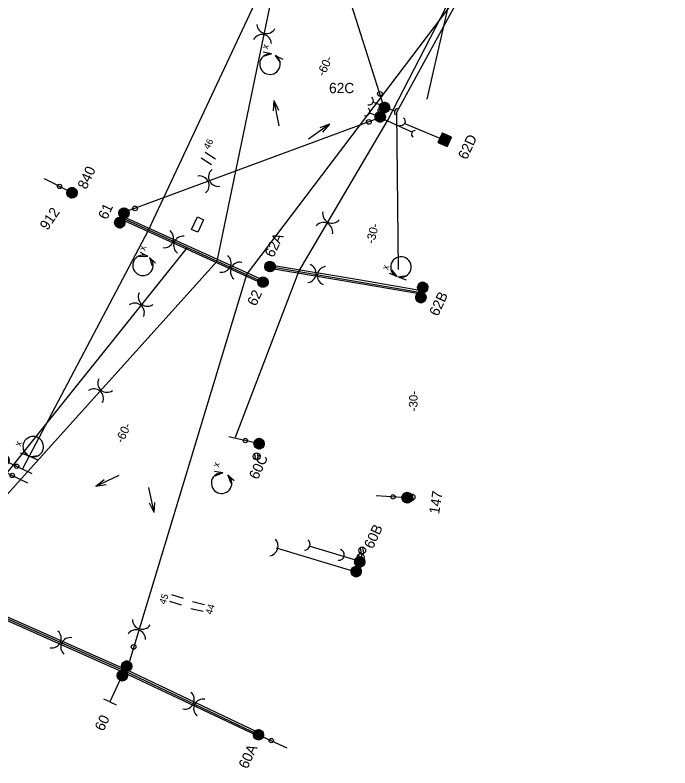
# Model space of a CAD drawing. Extents: x -595867 to -593796, y -1159595 to -1157495.
# Drawn here: x -594848.4 to -594752.7, y -1158325.2 to -1158215.3 of the extents above; entities that cross this region are included whole.
import ezdxf

# ---------------------------------------------------------------- set-up
doc = ezdxf.new("R2010")
doc.units = 0
doc.layers.add('BVK_kanalizace_destova_nova', color=7, linetype='Continuous')
doc.layers.add('BVK_kanalizace_jednotna_nova', color=7, linetype='Continuous')

# ---------------------------------------------------------------- blocks, each defined once
blk = doc.blocks.new('st_bp')
for p, q in [((0.0075, 0.0075), (-0.0075, 0.0075)), ((-0.0075, 0.0075), (-0.0075, -0.0075)), ((-0.0075, -0.0075), (0.0075, 0.0075)), ((-0.0075, -0.0071), (0.0071, 0.0075)), ((-0.0075, -0.0067), (0.0067, 0.0075)), ((-0.0075, -0.0062), (0.0062, 0.0075)), ((-0.0075, -0.0058), (0.0058, 0.0075)), ((-0.0075, -0.0054), (0.0054, 0.0075)), ((-0.0075, -0.005), (0.005, 0.0075)), ((-0.0075, -0.0045), (0.0045, 0.0075)), ((-0.0075, -0.0041), (0.0041, 0.0075)), ((-0.0075, -0.0037), (0.0037, 0.0075)), ((-0.0075, -0.0033), (0.0033, 0.0075)), ((-0.0075, -0.0028), (0.0028, 0.0075)), ((-0.0075, -0.0024), (0.0024, 0.0075)), ((-0.0075, -0.002), (0.002, 0.0075)), ((-0.0075, -0.0016), (0.0016, 0.0075)), ((-0.0075, -0.0011), (0.0011, 0.0075)), ((-0.0075, -0.0007), (0.0007, 0.0075)), ((-0.0075, -0.0003), (0.0003, 0.0075)), ((-0.0075, 0.0001), (-0.0001, 0.0075)), ((-0.0075, 0.0006), (-0.0006, 0.0075)), ((-0.0075, 0.001), (-0.001, 0.0075)), ((-0.0075, 0.0014), (-0.0014, 0.0075)), ((-0.0075, 0.0018), (-0.0018, 0.0075)), ((-0.0075, 0.0023), (-0.0023, 0.0075)), ((-0.0075, 0.0027), (-0.0027, 0.0075)), ((-0.0075, 0.0031), (-0.0031, 0.0075)), ((-0.0075, 0.0035), (-0.0035, 0.0075)), ((-0.0075, 0.004), (-0.004, 0.0075)), ((-0.0075, 0.0044), (-0.0044, 0.0075)), ((-0.0075, 0.0048), (-0.0048, 0.0075)), ((-0.0075, 0.0052), (-0.0052, 0.0075)), ((-0.0075, 0.0057), (-0.0057, 0.0075)), ((-0.0075, 0.0061), (-0.0061, 0.0075)), ((-0.0075, 0.0065), (-0.0065, 0.0075)), ((-0.0075, 0.0069), (-0.0069, 0.0075)), ((-0.0075, 0.0073), (-0.0073, 0.0075)), ((-0.0071, -0.0075), (0.0075, 0.0071)), ((-0.0067, -0.0075), (0.0075, 0.0067)), ((-0.0062, -0.0075), (0.0075, 0.0062)), ((-0.0058, -0.0075), (0.0075, 0.0058)), ((-0.0054, -0.0075), (0.0075, 0.0054)), ((-0.005, -0.0075), (0.0075, 0.005)), ((-0.0045, -0.0075), (0.0075, 0.0045)), ((-0.0041, -0.0075), (0.0075, 0.0041)), ((-0.0037, -0.0075), (0.0075, 0.0037)), ((-0.0033, -0.0075), (0.0075, 0.0033)), ((-0.0028, -0.0075), (0.0075, 0.0028)), ((-0.0024, -0.0075), (0.0075, 0.0024)), ((-0.002, -0.0075), (0.0075, 0.002)), ((-0.0016, -0.0075), (0.0075, 0.0016)), ((-0.0011, -0.0075), (0.0075, 0.0011)), ((-0.0007, -0.0075), (0.0075, 0.0007)), ((-0.0003, -0.0075), (0.0075, 0.0003)), ((0.0075, -0.0075), (0.0075, 0.0075)), ((-0.0075, -0.0075), (0.0075, -0.0075)), ((0.0001, -0.0075), (0.0075, -0.0001)), ((0.0006, -0.0075), (0.0075, -0.0006)), ((0.001, -0.0075), (0.0075, -0.001)), ((0.0014, -0.0075), (0.0075, -0.0014)), ((0.0018, -0.0075), (0.0075, -0.0018)), ((0.0023, -0.0075), (0.0075, -0.0023)), ((0.0027, -0.0075), (0.0075, -0.0027)), ((0.0031, -0.0075), (0.0075, -0.0031)), ((0.0035, -0.0075), (0.0075, -0.0035)), ((0.004, -0.0075), (0.0075, -0.004)), ((0.0044, -0.0075), (0.0075, -0.0044)), ((0.0048, -0.0075), (0.0075, -0.0048)), ((0.0052, -0.0075), (0.0075, -0.0052)), ((0.0057, -0.0075), (0.0075, -0.0057)), ((0.0061, -0.0075), (0.0075, -0.0061)), ((0.0065, -0.0075), (0.0075, -0.0065)), ((0.0069, -0.0075), (0.0075, -0.0069)), ((0.0073, -0.0075), (0.0075, -0.0073))]:
    blk.add_line(p, q)
blk = doc.blocks.new('st_2t')
for points in [[(-0.0077, 0.0091), (0.0015, 0.0147), (0.0025, 0.0144), (-0.0078, 0.0082)], [(-0.0078, 0.0082), (0.0025, 0.0144), (0.0032, 0.014), (-0.0078, 0.0072)], [(-0.0078, 0.0072), (0.0032, 0.014), (0.004, 0.0135), (-0.0078, 0.0065)], [(-0.0078, 0.0065), (0.004, 0.0135), (0.0048, 0.0129), (-0.0076, 0.0056)], [(-0.0075, 0.0097), (0.0002, 0.0149), (0.0015, 0.0147), (-0.0077, 0.0091)], [(-0.0076, 0.0056), (0.0048, 0.0129), (0.0055, 0.0121), (-0.0073, 0.0044)], [(-0.0073, 0.0104), (-0.0005, 0.015), (0.0002, 0.0149), (-0.0075, 0.0097)], [(-0.0071, 0.0108), (-0.0019, 0.0148), (-0.0005, 0.015), (-0.0073, 0.0104)], [(-0.0073, 0.0044), (0.0055, 0.0121), (0.0063, 0.0109), (-0.0068, 0.0036)], [(-0.0066, 0.0115), (-0.0026, 0.0146), (-0.0019, 0.0148), (-0.0071, 0.0108)], [(-0.0062, 0.0122), (-0.0035, 0.0142), (-0.0026, 0.0146), (-0.0066, 0.0115)], [(-0.0056, 0.0128), (-0.0045, 0.0137), (-0.0035, 0.0142), (-0.0062, 0.0122)], [(-0.0068, 0.0036), (0.0063, 0.0109), (0.0067, 0.0097), (-0.006, 0.0026)], [(-0.006, 0.0026), (0.0067, 0.0097), (0.007, 0.0086), (-0.0052, 0.0018)], [(-0.0052, 0.0018), (0.007, 0.0086), (0.0071, 0.0071), (-0.0044, 0.0012)], [(-0.0044, 0.0012), (0.0071, 0.0071), (0.0069, 0.0057), (-0.0035, 0.0007)], [(-0.0035, 0.0007), (0.0069, 0.0057), (0.0066, 0.0047), (-0.0024, 0.0003)], [(-0.0024, 0.0003), (0.0066, 0.0047), (0.0061, 0.0038), (-0.0015, 0.0001)], [(-0.0015, 0.0001), (0.0061, 0.0038), (0.0055, 0.0029), (-0.0009, 0)], [(-0.0009, 0), (0.0055, 0.0029), (0.005, 0.0022), (0, 0)], [(0, 0), (0.005, 0.0022), (0.0041, 0.0015), (0.001, 0.0001)], [(0.001, 0.0001), (0.0041, 0.0015), (0.0035, 0.001), (0.0021, 0.0004)], [(0.0021, 0.0004), (0.0035, 0.001), (0.0026, 0.0006), (0.0026, 0.0005)], [(-0.0077, -0.0059), (0.0015, -0.0003), (0.0025, -0.0006), (-0.0078, -0.0068)], [(-0.0078, -0.0068), (0.0025, -0.0006), (0.0032, -0.001), (-0.0078, -0.0078)], [(-0.0078, -0.0078), (0.0032, -0.001), (0.004, -0.0015), (-0.0078, -0.0085)], [(-0.0078, -0.0085), (0.004, -0.0015), (0.0048, -0.0021), (-0.0076, -0.0094)], [(-0.0075, -0.0053), (0.0002, -0.0001), (0.0015, -0.0003), (-0.0077, -0.0059)], [(-0.0076, -0.0094), (0.0048, -0.0021), (0.0055, -0.0029), (-0.0073, -0.0106)], [(-0.0073, -0.0046), (-0.0005, 0), (0.0002, -0.0001), (-0.0075, -0.0053)], [(-0.0071, -0.0042), (-0.0019, -0.0002), (-0.0005, 0), (-0.0073, -0.0046)], [(-0.0073, -0.0106), (0.0055, -0.0029), (0.0063, -0.0041), (-0.0068, -0.0114)], [(-0.0066, -0.0035), (-0.0026, -0.0004), (-0.0019, -0.0002), (-0.0071, -0.0042)], [(-0.0068, -0.0114), (0.0063, -0.0041), (0.0067, -0.0053), (-0.006, -0.0124)], [(-0.0062, -0.0028), (-0.0035, -0.0008), (-0.0026, -0.0004), (-0.0066, -0.0035)], [(-0.0056, -0.0022), (-0.0045, -0.0013), (-0.0035, -0.0008), (-0.0062, -0.0028)], [(-0.006, -0.0124), (0.0067, -0.0053), (0.007, -0.0064), (-0.0052, -0.0132)], [(-0.0052, -0.0132), (0.007, -0.0064), (0.0071, -0.0079), (-0.0044, -0.0138)], [(-0.0044, -0.0138), (0.0071, -0.0079), (0.0069, -0.0093), (-0.0035, -0.0143)], [(-0.0035, -0.0143), (0.0069, -0.0093), (0.0066, -0.0103), (-0.0024, -0.0147)], [(-0.0024, -0.0147), (0.0066, -0.0103), (0.0061, -0.0112), (-0.0015, -0.0149)], [(-0.0015, -0.0149), (0.0061, -0.0112), (0.0055, -0.0121), (-0.0009, -0.015)], [(-0.0009, -0.015), (0.0055, -0.0121), (0.005, -0.0128), (0, -0.015)], [(0, -0.015), (0.005, -0.0128), (0.0041, -0.0135), (0.001, -0.0149)], [(0.001, -0.0149), (0.0041, -0.0135), (0.0035, -0.014), (0.0021, -0.0146)], [(0.0021, -0.0146), (0.0035, -0.014), (0.0026, -0.0144), (0.0026, -0.0145)]]:
    blk.add_lwpolyline(points, close=True)
for centre in [(-0.0004, 0.0075), (-0.0004, -0.0075)]:
    blk.add_circle(centre, 0.0075)
blk = doc.blocks.new('st_1t')
for points in [[(-0.0074, 0.0007), (0.0028, 0.0069), (0.0036, 0.0066), (-0.0075, -0.0002)], [(-0.0075, -0.0002), (0.0036, 0.0066), (0.0044, 0.006), (-0.0074, -0.001)], [(-0.0073, 0.0016), (0.0019, 0.0072), (0.0028, 0.0069), (-0.0074, 0.0007)], [(-0.0074, -0.001), (0.0044, 0.006), (0.0052, 0.0054), (-0.0072, -0.0019)], [(-0.0071, 0.0022), (0.0006, 0.0074), (0.0019, 0.0072), (-0.0073, 0.0016)], [(-0.0072, -0.0019), (0.0052, 0.0054), (0.0059, 0.0046), (-0.0069, -0.003)], [(-0.0069, 0.0029), (-0.0001, 0.0075), (0.0006, 0.0074), (-0.0071, 0.0022)], [(-0.0067, 0.0033), (-0.0015, 0.0073), (-0.0001, 0.0075), (-0.0069, 0.0029)], [(-0.0069, -0.003), (0.0059, 0.0046), (0.0067, 0.0034), (-0.0064, -0.0039)], [(-0.0063, 0.004), (-0.0022, 0.0071), (-0.0015, 0.0073), (-0.0067, 0.0033)], [(-0.0064, -0.0039), (0.0067, 0.0034), (0.0071, 0.0022), (-0.0057, -0.0049)], [(-0.0058, 0.0047), (-0.0032, 0.0068), (-0.0022, 0.0071), (-0.0063, 0.004)], [(-0.0053, 0.0053), (-0.0041, 0.0062), (-0.0032, 0.0068), (-0.0058, 0.0047)], [(-0.0057, -0.0049), (0.0071, 0.0022), (0.0074, 0.0011), (-0.0049, -0.0056)], [(-0.0049, -0.0056), (0.0074, 0.0011), (0.0075, -0.0004), (-0.004, -0.0063)], [(-0.004, -0.0063), (0.0075, -0.0004), (0.0073, -0.0017), (-0.0032, -0.0068)], [(-0.0032, -0.0068), (0.0073, -0.0017), (0.007, -0.0027), (-0.0021, -0.0072)], [(-0.0021, -0.0072), (0.007, -0.0027), (0.0065, -0.0037), (-0.0011, -0.0074)], [(-0.0011, -0.0074), (0.0065, -0.0037), (0.0059, -0.0046), (-0.0005, -0.0075)], [(-0.0005, -0.0075), (0.0059, -0.0046), (0.0054, -0.0052), (0.0004, -0.0075)], [(0.0004, -0.0075), (0.0054, -0.0052), (0.0045, -0.006), (0.0014, -0.0074)], [(0.0014, -0.0074), (0.0045, -0.006), (0.0038, -0.0064), (0.0025, -0.007)], [(0.0025, -0.007), (0.0038, -0.0064), (0.0029, -0.0069), (0.0029, -0.0069)]]:
    blk.add_lwpolyline(points, close=True)
blk.add_circle((0, 0), 0.0075)
blk = doc.blocks.new('st_tecka')
blk.add_circle((0, 0), 0.00314)
blk = doc.blocks.new('st1k_konzola')
blk.add_line((0, 0), (0.0453, 0))
at = {"rotation": 90}
blk.add_blockref('st_tecka', (0.0205, 0), dxfattribs=at)
blk = doc.blocks.new('st_pk')
for p, q in [((0, 0), (0, -0.05)), ((0, -0.05), (-0.01, -0.05)), ((0, -0.05), (0.01, -0.05))]:
    blk.add_line(p, q)
blk = doc.blocks.new('st2k_2t')
for p, q in [((-0.0004, 0.0075), (0.0449, 0.0075)), ((-0.0004, -0.0075), (0.0449, -0.0075))]:
    blk.add_line(p, q)
blk.add_blockref('st_2t', (0, 0))
at = {"rotation": 90}
for p in [(0.0202, 0.0075), (0.0202, -0.0075)]:
    blk.add_blockref('st_tecka', p, dxfattribs=at)
blk = doc.blocks.new('st1k_1t')
blk.add_line((0, 0), (0.0453, 0))
blk.add_blockref('st_1t', (0, 0))
at = {"rotation": 90}
blk.add_blockref('st_tecka', (0.0205, 0), dxfattribs=at)
blk = doc.blocks.new('pol_delic')
for p, q in [((-0.005, -0.009), (-0.005, 0.009)), ((0.005, -0.009), (0.005, 0.009))]:
    blk.add_line(p, q)
blk = doc.blocks.new('pol_izol')
for centre, start, end in [((-0.0148, 0), 284.4047, 75.5953), ((0.0148, 0), 104.4047, 255.5953)]:
    blk.add_arc(centre, 0.0138, start, end)
blk = doc.blocks.new('pol_pevbod')
for q in [(0, 0), (0.0163, 0.0168), (0.0204, 0.0101)]:
    blk.add_line((0.0305, 0.0219), q)
blk = doc.blocks.new('pol_sjsp')
for p, q in [((-0.01, 0.005), (0.01, 0.005)), ((-0.01, -0.005), (-0.01, 0.005)), ((0.01, 0.005), (0.01, -0.005)), ((0.01, -0.005), (-0.01, -0.005))]:
    blk.add_line(p, q)
blk = doc.blocks.new('pol_sipka2')
for q in [(0.0123, 0.003), (0.0118, -0.0034)]:
    blk.add_line((0, 0), q)
blk = doc.blocks.new('kotv_tecka')
blk.add_circle((0, 0), 0.00345)

msp = doc.modelspace()

# ---------------------------------------------------------------- linework, layer by layer
at = {"layer": 'BVK_kanalizace_destova_nova'}
for p, q in [((-594828.86, -1158246.71), (-594803.38, -1158192.23)), ((-594818.87, -1158251.23), (-594806.72, -1158192.59)), ((-594794.45, -1158228.78), (-594806.08, -1158192.23)), ((-594793.92, -1158230.65), (-594779.48, -1158202.56)), ((-594792.64, -1158229.45), (-594778.14, -1158203.04)), ((-594814.56, -1158253.19), (-594777.44, -1158204.25)), ((-594794.53, -1158228.62), (-594796.03, -1158228.05)), ((-594794.11, -1158228.8), (-594792.96, -1158229.28)), ((-594795.03, -1158230.2), (-594796.54, -1158229.63)), ((-594792.38, -1158252.42), (-594792.64, -1158229.45)), ((-594795.39, -1158230.38), (-594831.84, -1158243.88)), ((-594806.95, -1158252.73), (-594793.92, -1158230.65)), ((-594794.96, -1158230.32), (-594790.34, -1158232.41)), ((-594785.7, -1158233.58), (-594791.56, -1158231.11)), ((-594832.73, -1158244.91), (-594812.16, -1158254.28)), ((-594847.21, -1158281.49), (-594828.86, -1158246.71)), ((-594823.24, -1158249.24), (-594861.61, -1158297.09)), ((-594818.87, -1158251.23), (-594860.71, -1158297.62)), ((-594811.15, -1158252), (-594789.01, -1158255.78)), ((-594814.56, -1158253.19), (-594831.67, -1158309.58)), ((-594816.16, -1158276.91), (-594806.95, -1158252.73)), ((-594797.98, -1158295.03), (-594805.44, -1158292.79)), ((-594798.57, -1158296.58), (-594810.19, -1158293.08)), ((-594832.42, -1158310.99), (-594861.62, -1158298.02)), ((-594812.82, -1158320.32), (-594832.42, -1158310.99))]:
    msp.add_line(p, q, dxfattribs=at)
msp.add_lwpolyline([(-594788.17, -1158227.59), (-594782.22, -1158201.34), (-594752.74, -1158134.87)], dxfattribs=at)
for centre, radius, start, end in [((-594811.15, -1158222.47), 1.5, 81.4667, 58.5434), ((-594796.66, -1158227.8), 0.617, 252.2502, 53.7021), ((-594797.16, -1158229.38), 0.617, 252.2502, 53.7021), ((-594792.36, -1158229.52), 0.616, 103.7803, 214.9269), ((-594791.98, -1158230.81), 0.609, 245.168, 54.996), ((-594789.93, -1158232.7), 0.552, 90.9789, 227.8195), ((-594829.68, -1158251.82), 1.5, 61.4361, 50.7237), ((-594792.02, -1158252.07), 1.5, 254.6573, 249.1556), ((-594845.71, -1158278.29), 1.5, 252.8457, 242.3483), ((-594818.21, -1158283.61), 1.5, 82.9588, 52.7814), ((-594811.39, -1158292.78), 1.44, 278.4346, 44.2733), ((-594806.11, -1158292.55), 0.818, 269.7856, 52.8408), ((-594801.08, -1158294.06), 0.786, 262.7484, 74.4017)]:
    msp.add_arc(centre, radius, start, end, dxfattribs=at)
at = {"layer": 'BVK_kanalizace_jednotna_nova'}
for p, q in [((-594794.98, -1158229.76), (-594795.14, -1158228.86)), ((-594794.61, -1158229.71), (-594794.78, -1158228.79)), ((-594795.41, -1158230.67), (-594795.57, -1158229.77)), ((-594795.04, -1158230.61), (-594795.2, -1158229.7)), ((-594784.97, -1158233.27), (-594786.29, -1158233.76)), ((-594785.45, -1158233.04), (-594786.07, -1158233.28)), ((-594785.19, -1158233.75), (-594785.81, -1158233.98)), ((-594832.62, -1158244.94), (-594832.78, -1158244.04)), ((-594832.25, -1158244.88), (-594832.41, -1158243.97)), ((-594833.04, -1158245.85), (-594833.2, -1158244.95)), ((-594832.67, -1158245.79), (-594832.83, -1158244.88)), ((-594811.25, -1158252.51), (-594811.41, -1158251.61)), ((-594810.88, -1158252.46), (-594811.05, -1158251.54)), ((-594812.26, -1158254.74), (-594812.42, -1158253.84)), ((-594811.89, -1158254.69), (-594812.06, -1158253.77)), ((-594788.88, -1158255.82), (-594789.04, -1158254.92)), ((-594788.51, -1158255.76), (-594788.67, -1158254.85)), ((-594789.32, -1158256.72), (-594789.48, -1158255.82)), ((-594788.95, -1158256.67), (-594789.11, -1158255.75)), ((-594813.2, -1158280.18), (-594813.36, -1158279.28)), ((-594812.83, -1158280.12), (-594812.99, -1158279.21)), ((-594790.58, -1158286.14), (-594790.74, -1158285.24)), ((-594790.21, -1158286.08), (-594790.38, -1158285.17)), ((-594797.79, -1158293.91), (-594797.95, -1158293.01)), ((-594797.63, -1158294.81), (-594797.8, -1158293.9)), ((-594797.42, -1158293.85), (-594797.58, -1158292.94)), ((-594798, -1158294.87), (-594798.16, -1158293.97)), ((-594832.33, -1158311.01), (-594832.49, -1158310.11)), ((-594831.96, -1158310.95), (-594832.13, -1158310.04)), ((-594832.74, -1158311.92), (-594832.9, -1158311.02)), ((-594832.37, -1158311.86), (-594832.54, -1158310.95)), ((-594812.96, -1158320.74), (-594813.12, -1158319.84)), ((-594812.59, -1158320.69), (-594812.76, -1158319.77))]:
    msp.add_line(p, q, dxfattribs=at)
msp.add_lwpolyline([(-594785.38, -1158234.17), (-594786.29, -1158233.75), (-594785.88, -1158232.85), (-594784.97, -1158233.26)], close=True, dxfattribs=at)
for points in [[(-594785.38, -1158234.17), (-594786.29, -1158233.75), (-594785.88, -1158232.85), (-594784.97, -1158233.26), (-594785.38, -1158234.17)], [(-594812.26, -1158254.49), (-594832.83, -1158245.14)], [(-594812.05, -1158254.03), (-594832.63, -1158244.68)], [(-594797.94, -1158254.01), (-594811.1, -1158251.78)], [(-594797.91, -1158254.53), (-594811.18, -1158252.28)], [(-594788.96, -1158255.53), (-594797.94, -1158254.01)], [(-594789.05, -1158256.03), (-594797.91, -1158254.53)], [(-594832.52, -1158311.22), (-594861.72, -1158298.25)], [(-594832.32, -1158310.76), (-594861.52, -1158297.79)], [(-594812.96, -1158320.48), (-594832.53, -1158311.22)], [(-594812.75, -1158320.03), (-594832.31, -1158310.76)]]:
    msp.add_lwpolyline(points, dxfattribs=at)
for centre in [(-594794.87, -1158229.28), (-594794.87, -1158229.28), (-594795.3, -1158230.19), (-594795.3, -1158230.19), (-594832.51, -1158244.46), (-594832.51, -1158244.46), (-594832.93, -1158245.37), (-594832.93, -1158245.37), (-594811.14, -1158252.03), (-594811.14, -1158252.03), (-594812.15, -1158254.26), (-594812.15, -1158254.26), (-594788.77, -1158255.34), (-594788.77, -1158255.34), (-594789.21, -1158256.24), (-594789.21, -1158256.24), (-594813.09, -1158279.7), (-594813.09, -1158279.7), (-594790.47, -1158285.66), (-594790.47, -1158285.66), (-594797.89, -1158294.39), (-594797.89, -1158294.39), (-594797.68, -1158293.43), (-594797.68, -1158293.43), (-594832.22, -1158310.52), (-594832.22, -1158310.52), (-594832.63, -1158311.44), (-594832.63, -1158311.44), (-594812.85, -1158320.26), (-594812.85, -1158320.26)]:
    msp.add_circle(centre, 0.5, dxfattribs=at)

# ---------------------------------------------------------------- block references
at = {"layer": 'BVK_kanalizace_destova_nova'}
for name, p, xscale, yscale, rotation in [('pol_izol', (-594811.98, -1158218.07), 100, 100.00000000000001, 77.49794741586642), ('pol_sipka2', (-594810.93, -1158220.98), 100, 100, -176.01483008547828), ('pol_sipka2', (-594810.37, -1158221.19), 99.99999999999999, -100.00000000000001, -41.95355688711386), ('kotv_tecka', (-594795.09, -1158226.8), 100.00000000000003, 99.99999999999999, 79.51685128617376), ('pol_pevbod', (-594809.84, -1158231.45), 100, 100.00000000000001, 65.41114768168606), ('st_2t', (-594794.7, -1158229.48), 100, 100, -24.5888523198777), ('pol_pevbod', (-594805.51, -1158233.4), 100, 99.99999999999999, -0.5167056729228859), ('kotv_tecka', (-594796.71, -1158230.9), 100.00000000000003, 99.99999999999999, 79.51685128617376), ('st_bp', (-594785.63, -1158233.51), 100, 100, 155.44043859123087), ('pol_delic', (-594820.14, -1158236.26), 100.00000000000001, 99.99999999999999, 56.88639590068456), ('pol_izol', (-594820.07, -1158239.54), 100, 100.00000000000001, 24.829460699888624), ('st1k_1t', (-594840.05, -1158241.24), 99.99999999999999, 100.00000000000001, 152.92029311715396), ('st_2t', (-594832.73, -1158244.91), 100, 100, -24.202520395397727), ('kotv_tecka', (-594830.85, -1158243.51), 100.00000000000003, 99.99999999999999, 79.51685128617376), ('pol_izol', (-594802.72, -1158245.62), 100, 100, 64.0793756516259), ('pol_sjsp', (-594821.71, -1158245.88), 100.00000000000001, 100, 65.41114768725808), ('pol_izol', (-594825.21, -1158248.41), 100, 99.99999999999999, -21.40684368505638), ('pol_sipka2', (-594828.96, -1158250.51), 100, 100, 169.21811465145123), ('pol_sipka2', (-594828.73, -1158250.66), 100, -100, -59.57596215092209), ('pol_izol', (-594816.87, -1158252.1), 100, 99.99999999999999, -26.09730343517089), ('st_1t', (-594811.15, -1158252), 100.00000000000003, 99.99999999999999, 79.51685128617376), ('pol_izol', (-594804.32, -1158253.17), 99.99999999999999, 100.00000000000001, -7.379715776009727), ('pol_sipka2', (-594792.56, -1158253.47), 100, -100.00000000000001, 141.45730821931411), ('pol_sipka2', (-594792.42, -1158253.51), 100.00000000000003, 99.99999999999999, -3.835482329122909), ('st_1t', (-594812.16, -1158254.28), 100.00000000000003, 99.99999999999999, 79.51685128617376), ('st_2t', (-594789.01, -1158255.78), 100.00000000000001, 99.99999999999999, 169.87951282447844), ('pol_izol', (-594829.93, -1158257.57), 99.99999999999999, 100, 50.79977824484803), ('pol_izol', (-594835.88, -1158270.1), 99.99999999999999, 100.00000000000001, 49.475999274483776), ('st1k_1t', (-594812.73, -1158277.85), 100, 100.00000000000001, 167.06944859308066), ('st2k_2t', (-594850.27, -1158280.94), 99.99999999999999, 100.00000000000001, -25.4843226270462), ('pol_sipka2', (-594846.4, -1158279.62), 100.00000000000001, -100, 145.67571169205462), ('pol_sipka2', (-594846.15, -1158279.72), 100, 100, -7.724790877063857), ('pol_sipka2', (-594818.03, -1158282.12), 100, 100, -173.18298535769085), ('pol_pevbod', (-594833.16, -1158282.44), 100, 100, 169.8021555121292), ('pol_sipka2', (-594817.31, -1158282.42), 100, -99.99999999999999, -55.389348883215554), ('pol_pevbod', (-594828.84, -1158284.24), 100, 100, -113.57559142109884), ('st1k_1t', (-594791.12, -1158285.73), 100, 100.00000000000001, 176.52832137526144), ('st_2t', (-594798.26, -1158295.81), 100, 100.00000000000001, -20.350229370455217), ('pol_delic', (-594824.77, -1158300.65), 100.00000000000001, 100, 72.1955831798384), ('pol_delic', (-594821.69, -1158301.63), 100, 100.00000000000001, 77.41475921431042), ('pol_izol', (-594830.26, -1158304.96), 100, 100.00000000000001, 72.83729867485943), ('pol_izol', (-594841.65, -1158306.89), 100, 100, -25.20950787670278), ('kotv_tecka', (-594831.05, -1158307.51), 100.00000000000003, 99.99999999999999, 79.51685128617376), ('st_2t', (-594832.42, -1158310.99), 100.00000000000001, 99.99999999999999, 155.51186140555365), ('st_pk', (-594832.42, -1158310.99), 100.00000000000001, 99.99999999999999, -24.73966548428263), ('pol_izol', (-594822.24, -1158315.84), 99.99999999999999, 100.00000000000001, -25.906861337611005), ('st_1t', (-594812.82, -1158320.32), 100.00000000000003, 99.99999999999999, 79.51685128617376), ('st1k_konzola', (-594812.82, -1158320.32), 99.99999999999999, 100.00000000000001, -24.588852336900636)]:
    msp.add_blockref(name, p, dxfattribs=dict(at, xscale=xscale, yscale=yscale, rotation=rotation))

# ---------------------------------------------------------------- texts
for s, height, rotation, p in [('x', 1, 71.6034, (-594811.48, -1158220.36)), ('-60-', 1.25, 65.0264, (-594803.22, -1158224.35)), ('46', 1, 61.8346, (-594820.05, -1158234.99)), ('62D', 1.5, 65.0264, (-594782.41, -1158236.51)), ('840', 1.5, 65.0264, (-594837.96, -1158240.85)), ('61', 1.5, 65.0264, (-594834.96, -1158245.26)), ('-30-', 1.25, 76.4337, (-594795.93, -1158248.77)), ('62A', 1.5, 65.0264, (-594810.64, -1158250.79)), ('x', 1, 71.6034, (-594829.39, -1158249.78)), ('x', 1, 71.6034, (-594793.9, -1158252.58)), ('62', 1.5, 65.0264, (-594813.19, -1158257.88)), ('62B', 1.5, 65.0264, (-594786.62, -1158259.35)), ('62B', 1.5, 65.0264, (-594786.62, -1158259.35)), ('62B', 1.5, 65.0264, (-594786.62, -1158259.35)), ('-30-', 1.25, 88.6248, (-594789.63, -1158273.14)), ('-60-', 1.25, 65.0264, (-594832.63, -1158277.87)), ('x', 1, 71.6034, (-594847.54, -1158278.3)), ('60C', 1.5, 65.0264, (-594812.93, -1158283.19)), ('x', 1, 71.6034, (-594818.63, -1158281.35)), ('147', 1.5, 80.7627, (-594786.46, -1158288.19)), ('60B', 1.5, 65.0264, (-594796.13, -1158293.3)), ('45', 1, 71.6034, (-594826.4, -1158301.36)), ('44', 1, 71.6034, (-594819.65, -1158302.87)), ('60', 1.5, 65.0264, (-594835.45, -1158319.9)), ('60A', 1.5, 65.0264, (-594814.45, -1158325.4))]:
    msp.add_text(s, height=height, rotation=rotation, dxfattribs=at).set_placement(p)
at = {"layer": 'BVK_kanalizace_jednotna_nova'}
msp.add_text('62C', height=1.5, dxfattribs=at).set_placement((-594802.52, -1158226.7))
msp.add_text('912', height=1.5, rotation=56, dxfattribs=at).set_placement((-594843.63, -1158246.81))

doc.saveas('drawing.dxf')
